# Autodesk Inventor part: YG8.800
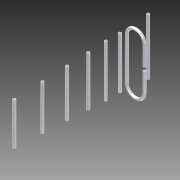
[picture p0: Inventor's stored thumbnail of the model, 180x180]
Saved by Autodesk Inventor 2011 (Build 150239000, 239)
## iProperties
Created: 2014-03
Part Number: YG8.800
Document SubType Name: Modeling
Designer: Evgeny
Density: 1 g/cm^3
Author: Evgeny
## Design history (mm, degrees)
sketch "Эскиз2"
  geometry: C1 r 4 at (0, 0); C2 r 3 at (0, 0); C3 r 4 at (0, -60); C4 r 3 at (0, -60); C5 r 4 at (0, 20); C6 r 3 at (0, 20); C7 r 4 at (0, 60); C8 r 3 at (0, 60); C9 r 4 at (0, 110); C10 r 3 at (0, 110); C11 r 4 at (0, 170); C12 r 3 at (0, 170); C13 r 4 at (0, 240); C14 r 3 at (0, 240); C15 r 4 at (0, 320); C16 r 3 at (0, 320); 1 further point
  constraints: 16 centre point, 9 coincident
  dimensions: "d0" = 8 diameter of C1; "d1" = 6 diameter of C2; "d2" = 8 diameter of C3; "d3" = 6 diameter of C4; "d4" = 8 diameter of C5; "d5" = 6 diameter of C6; "d6" = 8 diameter of C7; "d7" = 6 diameter of C8; "d8" = 8 diameter of C9; "d9" = 6 diameter of C10; "d10" = 8 diameter of C11; "d11" = 6 diameter of C12; "d12" = 8 diameter of C13; "d13" = 6 diameter of C14; "d14" = 8 diameter of C15; "d15" = 6 diameter of C16; "d16" = 60 distance of C3.centre point (0, 0); "d17" = 20 distance of C5.centre point (0, 0); "d18" = 60 distance of C7.centre C1.centre; "d19" = 110 distance of C9.centre point (0, 0); "d20" = 170 distance of C11.centre point (0, 0); "d21" = 240 distance of C13.centre C1.centre; "d22" = 320 distance of C15.centre point (0, 0)
extrude "Выдавливание1" new body sketch "Эскиз2" stored distance "d23" = 160; taper "d24" = 0 deg
extrude "Выдавливание2" join sketch "Эскиз2" stored distance "d25" = 146; taper "d26" = 0 deg
extrude "Выдавливание3" join sketch "Эскиз2" stored distance "d27" = 147; taper "d28" = 0 deg
extrude "Выдавливание4" join sketch "Эскиз2" stored distance "d29" = 141; taper "d30" = 0 deg
extrude "Выдавливание6" join sketch "Эскиз2" stored distance "d33" = 134; taper "d34" = 0 deg
extrude "Выдавливание7" join sketch "Эскиз2" stored distance "d35" = 127; taper "d36" = 0 deg
extrude "Выдавливание8" join sketch "Эскиз2" stored distance "d37" = 120; taper "d38" = 0 deg
sketch "Эскиз3"
  geometry: L1 (24, 84.5)-(26, 84.5); L2 (26, -84.5)-(24, -84.5); L3 (0, -60.5)-(0, 60.5); L4 (50, 60.5)-(50, 5); L5 (50, -5)-(50, -60.5); A1 r 24 centre (24, 60.5) between (24, 84.5) and (0, 60.5); A2 r 24 centre (26, 60.5) between (50, 60.5) and (26, 84.5); A3 r 24 centre (26, -60.5) between (26, -84.5) and (50, -60.5); A4 r 24 centre (24, -60.5) between (0, -60.5) and (24, -84.5); 1 further point
  constraints: 10 end point, 10 tangent, 8 point on circle, 4 centre point, 3 equal radius, 3 parallel, 2 perpendicular, 1 horizontal
  dimensions: "d50" = 169 distance between parallel lines of L1 L2; "d51" = 84.5 distance from line of point (0, 0) L2; "d52" = 24 radius of A1; "d53" = 5 vertical distance of L4.end point (0, 0); "d54" = 10 distance of L5.start L4.end
feature "Сдвиг1" sketch "Эскиз3" dims "d55" = 0
node "Твердое тело1"
